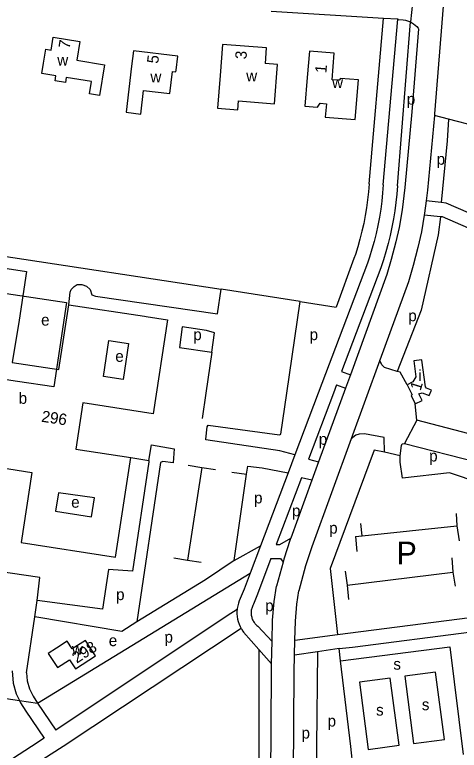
# Model space of a CAD drawing. Extents: x 161093 to 163177, y 379000 to 380904.
# Drawn here: x 162069 to 162225.3, y 380098.6 to 380357.5 of the extents above; entities that cross this region are included whole.
import ezdxf

# ---------------------------------------------------------------- set-up
doc = ezdxf.new("R2010")
doc.units = 0
for name, color, linetype in [('BLT_Basislijn', 7, 'Continuous'), ('BLT_Bebouwing', 7, 'Continuous'), ('BLT_Centroide', 7, 'Continuous'), ('BLT_Huisnummer', 7, 'Continuous'), ('BLT_Plantopo', 7, 'Continuous'), ('BLT_Tekst_parkeren', 7, 'Continuous'), ('BLT_Vlakafsluiter', 7, 'Continuous')]:
    doc.layers.add(name, color=color, linetype=linetype)

msp = doc.modelspace()

# ---------------------------------------------------------------- linework, layer by layer
at = {"layer": 'BLT_Basislijn'}
for p, q in [((162198.67, 380356.2), (162159.21, 380358.65)), ((162193.58, 380297.98), (162198.67, 380356.2)), ((162198.57, 380297.66), (162203.66, 380355.89)), ((162203.66, 380355.89), (162198.67, 380356.2)), ((162203.56, 380297.34), (162208.14, 380354.96)), ((162203.9, 380355.88), (162203.66, 380355.89)), ((162221.51, 380320.74), (162216.57, 380322.02)), ((162236.18, 380316.92), (162221.51, 380320.74)), ((162218.96, 380291.4), (162213.66, 380291.97)), ((162218.68, 380286.4), (162213, 380287.01)), ((162020.09, 380279.33), (162141.64, 380260.89)), ((162192.98, 380270.01), (162175.72, 380224.32)), ((162188.26, 380271.65), (162181.99, 380254.57)), ((162197.7, 380268.37), (162183.94, 380231.94)), ((162140.29, 380252.19), (162141.64, 380260.89)), ((162169.35, 380256.53), (162141.64, 380260.89)), ((162164.68, 380224.32), (162169.35, 380256.53)), ((162169.35, 380256.53), (162181.99, 380254.57)), ((162138.36, 380238.71), (162136.21, 380224.32)), ((162203.49, 380231.99), (162198.95, 380233.34)), ((162183.94, 380231.94), (162187, 380230.81)), ((162182.18, 380227.27), (162181.07, 380224.32)), ((162182.18, 380227.27), (162185.29, 380226.11)), ((162136.21, 380224.32), (162134.88, 380215.35)), ((162175.72, 380224.32), (162167.53, 380202.64)), ((162210.33, 380214.78), (162209.83, 380220.58)), ((162167.53, 380202.64), (162165.1, 380196.22)), ((162204.46, 380202.3), (162198.96, 380203.58)), ((162109.79, 380201.62), (162116.21, 380200.61)), ((162134.8, 380198.19), (162129.74, 380165.58)), ((162129.99, 380198.94), (162134.8, 380198.19)), ((162134.8, 380198.19), (162139.61, 380197.45)), ((162145.3, 380196.56), (162150.49, 380195.76)), ((162146.18, 380165.42), (162150.49, 380195.76)), ((162165.1, 380196.22), (162155.43, 380170.61)), ((162191.17, 380174.08), (162190.71, 380178.48)), ((162188.76, 380173.83), (162189.31, 380168.57)), ((162146.18, 380165.42), (162155.43, 380170.61)), ((162155.43, 380170.61), (162151.78, 380160.93)), ((162124.93, 380166.33), (162129.74, 380165.58)), ((162159.06, 380166.08), (162154.33, 380153.55)), ((162129.74, 380165.58), (162134.55, 380164.84)), ((162151.78, 380160.93), (162149.65, 380155.3)), ((162185.88, 380156.7), (162223.07, 380161.31)), ((162149.65, 380155.3), (162147.97, 380151.24)), ((162154.33, 380153.55), (162152.99, 380150.11)), ((162152.19, 380147.9), (162152.14, 380147.56)), ((162152.25, 380148.24), (162152.19, 380147.9)), ((162152.34, 380148.57), (162152.25, 380148.24)), ((162152.43, 380148.9), (162152.34, 380148.57)), ((162152.56, 380149.22), (162152.43, 380148.9)), ((162152.69, 380149.54), (162152.56, 380149.22)), ((162152.99, 380150.11), (162152.69, 380149.54)), ((162152.13, 380147.22), (162152.12, 380146.87)), ((162152.12, 380146.87), (162152.14, 380146.53)), ((162152.14, 380147.56), (162152.13, 380147.22)), ((162152.14, 380146.53), (162152.17, 380146.19)), ((162152.17, 380146.19), (162152.24, 380145.85)), ((162152.24, 380145.85), (162152.31, 380145.51)), ((162152.31, 380145.51), (162152.41, 380145.18)), ((162182.5, 380139.33), (162228.95, 380145.32)), ((162152.41, 380145.18), (162152.52, 380144.86)), ((162152.52, 380144.86), (162152.66, 380144.54)), ((162152.66, 380144.54), (162152.8, 380144.23)), ((162152.8, 380144.23), (162152.98, 380143.93)), ((162152.98, 380143.93), (162153.16, 380143.64)), ((162153.16, 380143.64), (162153.37, 380143.37)), ((162153.37, 380143.37), (162153.58, 380143.1)), ((162153.58, 380143.1), (162153.82, 380142.85)), ((162153.82, 380142.85), (162154.07, 380142.6)), ((162154.07, 380142.6), (162154.47, 380142.27)), ((162149.48, 380140.22), (162154.88, 380134.06)), ((162154.47, 380142.27), (162159.49, 380136.92)), ((162187.76, 380134.97), (162229.62, 380140.36)), ((162167.5, 380137.4), (162182.5, 380139.33)), ((162167.37, 380132.08), (162167.5, 380137.4)), ((162183.04, 380134.42), (162187.76, 380134.97)), ((162154.88, 380134.06), (162154.71, 380069.15)), ((162154.88, 380134.06), (162159.3, 380129.04)), ((162175.45, 380133.29), (162167.37, 380132.08)), ((162183.04, 380134.42), (162175.45, 380133.29)), ((162183.55, 380130.14), (162183.04, 380134.42))]:
    msp.add_line(p, q, dxfattribs=at)
for points in [[(162221.79, 380386.84), (162216.62, 380322.6), (162216.57, 380322.02)], [(162203.9, 380355.88), (162205.62, 380355.66), (162206.38, 380355.55), (162207.13, 380355.36), (162207.85, 380355.1), (162208.14, 380354.96)], [(162208.14, 380354.96), (162208.55, 380354.76), (162209.2, 380354.35), (162209.81, 380353.88), (162210.37, 380353.34), (162210.87, 380352.75), (162211, 380352.55)], [(162211, 380352.55), (162208.65, 380323.29), (162206.21, 380296.69), (162205.19, 380288.78), (162204.17, 380282.61), (162203, 380277.52), (162201.4, 380271.38), (162199.83, 380266.05), (162187, 380230.81)], [(162216.57, 380322.02), (162214.16, 380295.81), (162213.66, 380291.97)], [(162221.51, 380320.74), (162220.98, 380313.14), (162218.96, 380291.4)], [(162193.58, 380297.98), (162193.36, 380295.17), (162193.06, 380292.37), (162192.68, 380289.58), (162192.22, 380286.8), (162191.69, 380284.03), (162191.07, 380281.28), (162190.38, 380278.55), (162189.61, 380275.84), (162188.77, 380273.15), (162188.26, 380271.65)], [(162198.57, 380297.66), (162198.34, 380294.78), (162198.04, 380291.91), (162197.66, 380289.05), (162197.2, 380286.2), (162196.66, 380283.36), (162196.04, 380280.54), (162195.34, 380277.74), (162194.57, 380274.96), (162193.71, 380272.2), (162192.98, 380270.01)], [(162203.56, 380297.34), (162203.33, 380294.4), (162203.02, 380291.46), (162202.64, 380288.53), (162202.17, 380285.61), (162201.62, 380282.7), (162201, 380279.81), (162200.3, 380276.94), (162199.52, 380274.09), (162198.67, 380271.26), (162197.7, 380268.37)], [(162213.66, 380291.97), (162213.1, 380287.62), (162213, 380287.01)], [(162244.29, 380280.93), (162220.69, 380291.21), (162218.96, 380291.4)], [(162213, 380287.01), (162212.02, 380281.07), (162210.77, 380275.62), (162209.11, 380269.24), (162207.44, 380263.55), (162197.39, 380235.98)], [(162218.68, 380286.4), (162217.84, 380280), (162211.85, 380253.56), (162203.49, 380231.99)], [(162242.29, 380276.35), (162219.39, 380286.32), (162218.68, 380286.4)], [(162088.01, 380255.45), (162088.48, 380259.87), (162088.86, 380260.77), (162089.9, 380261.91), (162090.95, 380262.51), (162092.59, 380262.53), (162094.23, 380261.99), (162095.57, 380260.74), (162096.11, 380258.89), (162097.39, 380258.51), (162140.29, 380252.19)], [(162139.27, 380245.53), (162136.39, 380246.41), (162127.92, 380247.62), (162126.93, 380240.4), (162138.36, 380238.71)], [(162138.36, 380238.71), (162139.27, 380245.53)], [(162197.39, 380235.98), (162187.29, 380208.23)], [(162198.95, 380233.34), (162198.5, 380233.81), (162198.11, 380234.33), (162197.79, 380234.89), (162197.53, 380235.49), (162197.39, 380235.98)], [(162187, 380230.81), (162185.29, 380226.11)], [(162206.92, 380227.27), (162204.52, 380231.68), (162203.49, 380231.99)], [(162185.29, 380226.11), (162175.83, 380200.15)], [(162167.53, 380202.64), (162162.24, 380204.03), (162136.25, 380207.85), (162136.14, 380208.09), (162136.64, 380212.45), (162136.98, 380213.03), (162162.05, 380209.65), (162162.59, 380209.92), (162164.68, 380224.32)], [(162181.07, 380224.32), (162172.27, 380201.04), (162175.83, 380200.15)], [(162260.16, 380201.73), (162210.33, 380214.78)], [(162198.96, 380203.58), (162198.94, 380208.72), (162191.94, 380210.05), (162190.13, 380209.93), (162188.95, 380209.48), (162187.29, 380208.23)], [(162187.29, 380208.23), (162173.43, 380170.19), (162171.26, 380163.55), (162168.87, 380154.72)], [(162116.21, 380200.61), (162117.09, 380206.11), (162125.12, 380204.76), (162124.69, 380199.76)], [(162204.46, 380202.3), (162205.01, 380205.92), (162205.25, 380206.43), (162206.06, 380206.62)], [(162206.06, 380206.62), (162231.66, 380200.03)], [(162198.96, 380203.58), (162195.39, 380204.28), (162179.93, 380162.57), (162182.5, 380139.33)], [(162232.64, 380192.64), (162221.84, 380196.26), (162205.39, 380194.4), (162204.51, 380200.02), (162204.46, 380202.3)], [(162116.21, 380200.61), (162116.14, 380200.16), (162110.4, 380161.64), (162102.02, 380162.27), (162099.86, 380148.35), (162076.87, 380151.37)], [(162124.69, 380199.76), (162121.1, 380200.26), (162120.28, 380199.95), (162111.97, 380143.83)], [(162175.83, 380200.15), (162173.47, 380193.68)], [(162150.49, 380195.76), (162151.02, 380198.65), (162155.97, 380197.99), (162165.1, 380196.22)], [(162173.47, 380193.68), (162169.82, 380194.56), (162160.95, 380171.08)], [(162173.47, 380193.68), (162166.06, 380173.32)], [(162224.19, 380182), (162224.45, 380177.57), (162225.21, 380172.34)], [(162188.76, 380173.83), (162191.17, 380174.08), (162224.45, 380177.57)], [(162160.95, 380171.08), (162162.24, 380171.08), (162166.06, 380173.32)], [(162166.06, 380173.32), (162165.87, 380172.81), (162163.59, 380165.84), (162163.33, 380164.87)], [(162159.06, 380166.08), (162162.49, 380166.08), (162163.33, 380164.87)], [(162222.65, 380166.33), (162223.07, 380161.31), (162223.86, 380156.41)], [(162146.18, 380165.42), (162136.05, 380158.64), (162111.97, 380143.83)], [(162163.33, 380164.87), (162161.03, 380156.4)], [(162076.87, 380151.37), (162077.88, 380159.45), (162056.85, 380162.52)], [(162077.06, 380115.17), (162151.78, 380160.93)], [(162185.23, 380161.61), (162185.88, 380156.7), (162186.38, 380151.69)], [(162159.49, 380136.92), (162159.67, 380144.48), (162160.18, 380151.04), (162161.03, 380156.4)], [(162167.5, 380137.4), (162167.66, 380144.07), (162168.13, 380150.1), (162168.87, 380154.72)], [(162076.05, 380145.6), (162076.87, 380151.37)], [(162147.97, 380151.24), (162147.64, 380150.36), (162147.39, 380149.46), (162147.22, 380148.54), (162147.18, 380148.14)], [(162147.18, 380148.14), (162143.66, 380146), (162083.49, 380105.73)], [(162147.18, 380148.14), (162147.13, 380147.61), (162147.12, 380146.68), (162147.19, 380145.74), (162147.33, 380144.82), (162147.56, 380143.91), (162147.86, 380143.03), (162148.24, 380142.17), (162148.61, 380141.5)], [(162073.21, 380125.83), (162076.05, 380145.6)], [(162111.97, 380143.83), (162106.63, 380140.39), (162076.05, 380145.6)], [(162148.61, 380141.5), (162086.06, 380100), (162046.53, 380074.71)], [(162148.61, 380141.5), (162148.69, 380141.35), (162149.2, 380140.58), (162149.48, 380140.22)], [(162159.3, 380129.04), (162159.49, 380136.92)], [(162183.55, 380130.14), (162221.93, 380135.08), (162226.6, 380097.18)], [(162175.45, 380133.29), (162175.12, 380100), (162175.06, 380082.63)], [(162166.71, 380035.59), (162167.23, 380126.08), (162167.37, 380132.08)], [(162187.95, 380092.23), (162187.16, 380100), (162183.55, 380130.14)], [(162051.68, 380129.25), (162049.48, 380119.32), (162070.67, 380116.13)], [(162158.8, 380050.8), (162159.23, 380126.2), (162159.3, 380129.04)], [(162068.14, 380126.64), (162068.43, 380122.21), (162069.56, 380118.51), (162070.67, 380116.13)], [(162073.21, 380125.83), (162073.39, 380123.11), (162074.25, 380120.3), (162075.46, 380117.68), (162077.06, 380115.17)], [(162220.1, 380102.44), (162216.98, 380126.1), (162206.1, 380124.67), (162209.23, 380101.01), (162220.1, 380102.44)], [(162204.18, 380100.39), (162201.05, 380124.05), (162190.18, 380122.61), (162193.31, 380098.95), (162204.18, 380100.39)], [(162070.67, 380116.13), (162071.06, 380115.28), (162072.88, 380112.42), (162079.34, 380102.95)], [(162070.67, 380116.13), (162077.06, 380115.17)], [(162077.06, 380115.17), (162083.49, 380105.73)], [(162079.34, 380102.95), (162074.93, 380100), (161992.28, 380046.37), (161988.3, 380044.19), (161984.8, 380043.84), (161981.68, 380045.04), (161979.21, 380047.82), (161978.69, 380048.91)]]:
    msp.add_lwpolyline(points, dxfattribs=at)
at = {"layer": 'BLT_Bebouwing'}
for points in [[(162095.3, 380329.63), (162096.02, 380334.01), (162087.16, 380335.46), (162086.87, 380333.66), (162083.23, 380334.26), (162083.52, 380336.05), (162078.52, 380336.87), (162079.1, 380340.44), (162079.92, 380345.39), (162081.82, 380345.08), (162082.56, 380349.59), (162091.88, 380348.07), (162090.8, 380341.46), (162100.57, 380339.86), (162098.81, 380329.06), (162095.3, 380329.63)], [(162114.34, 380330.85), (162123.53, 380329.76), (162124.45, 380337.52), (162125.7, 380337.37), (162125.77, 380337.94), (162126.36, 380342.91), (162110.76, 380344.76), (162110.12, 380339.37), (162108.2, 380323.16), (162113.35, 380322.55), (162114.34, 380330.85)], [(162157.12, 380340.32), (162157.55, 380345.84), (162142.07, 380347.04), (162141.22, 380336.13), (162140.3, 380324.58), (162147.42, 380324.02), (162147.66, 380327.17), (162160.31, 380326.19), (162161.38, 380339.99), (162157.11, 380340.32)], [(162178.2, 380321.49), (162188.66, 380320.59), (162189.87, 380334.54), (162183.52, 380335.09), (162183.06, 380334.43), (162180.56, 380334.64), (162181.35, 380343.93), (162172.65, 380344.69), (162171.85, 380335.4), (162170.98, 380325.35), (162175.43, 380324.97), (162176.43, 380326.39), (162178.61, 380326.2), (162178.2, 380321.49)], [(162019.55, 380237.6), (162021.39, 380250.01), (162025.13, 380274.47), (162073.2, 380267.11), (162070.58, 380249.99), (162068.08, 380235.11), (162084.57, 380232.59), (162088.01, 380255.45)], [(162088.01, 380255.45), (162114.67, 380251.37), (162115.18, 380251.29), (162122.74, 380250.14), (162117.68, 380217.08), (162092.99, 380220.86), (162090.49, 380204.57), (162109.79, 380201.62)], [(162102.13, 380242.84), (162109.03, 380241.82), (162107.09, 380229.15), (162100.21, 380230.2), (162102.13, 380242.84)], [(162209.83, 380220.58), (162212.19, 380221.76), (162211.04, 380224.08), (162212.2, 380224.45), (162214.69, 380223.45), (162215.47, 380225.36), (162213.81, 380226.04), (162213.4, 380226.58), (162212.1, 380235.88), (162212.08, 380236.05), (162209.27, 380235.67), (162210.02, 380230.09), (162208.94, 380228.25), (162206.92, 380227.27)], [(162206.92, 380227.27), (162208.68, 380223.69), (162208.35, 380223.52), (162209.83, 380220.58)], [(162023.21, 380200.46), (162021.87, 380191.72), (162021.53, 380189.53), (162020.84, 380185.02), (162055.79, 380179.67), (162058.74, 380198.93), (162075.05, 380196.43), (162071.27, 380171.72), (162104.44, 380166.65), (162109.79, 380201.62)], [(162097.42, 380131.86), (162093.84, 380137.31), (162089.25, 380134.3), (162087.42, 380137.08), (162083.66, 380134.61)], [(162083.66, 380134.61), (162080.81, 380132.73), (162084.09, 380127.74), (162088.3, 380130.51), (162090.43, 380127.27), (162097.42, 380131.86)]]:
    msp.add_lwpolyline(points, dxfattribs=at)
msp.add_lwpolyline([(162084.4, 380189.29), (162083.4, 380182.74), (162095.99, 380180.81), (162097.01, 380187.52)], close=True, dxfattribs=at)
at = {"layer": 'BLT_Plantopo'}
msp.add_line((162082.8, 380226.57), (162069.94, 380228.4), dxfattribs=at)
msp.add_lwpolyline([(162069.94, 380228.4), (162025.54, 380235.2), (162030, 380264.81), (162087.26, 380256.18), (162082.8, 380226.57)], dxfattribs=at)
at = {"layer": 'BLT_Vlakafsluiter'}
for p, q in [((162208.84, 380361.58), (162208.14, 380354.96)), ((162210.33, 380214.78), (162206.06, 380206.62))]:
    msp.add_line(p, q, dxfattribs=at)

# ---------------------------------------------------------------- texts
at = {"layer": 'BLT_Centroide'}
for s, p in [('w', (162083.97, 380339.6)), ('w', (162150.39, 380334.03)), ('w', (162116.71, 380333.66)), ('w', (162180.58, 380331.69)), ('p', (162206.83, 380325.85)), ('p', (162217.34, 380304.71)), ('p', (162207.35, 380249.63)), ('e', (162078.29, 380248.11)), ('p', (162131.77, 380242.97)), ('p', (162172.67, 380242.97)), ('e', (162104.37, 380235.34)), ('i', (162210.94, 380228.54)), ('b', (162070.41, 380220.56)), ('p', (162175.91, 380206.16)), ('p', (162214.7, 380200.27)), ('e', (162088.86, 380184)), ('p', (162153.15, 380185.51)), ('p', (162166.49, 380180.98)), ('p', (162179.55, 380174.89)), ('p', (162104.65, 380151.48)), ('p', (162157.06, 380147.58)), ('e', (162102.08, 380135.28)), ('p', (162121.66, 380136.52)), ('w', (162089.12, 380132.28)), ('s', (162202.12, 380126.99)), ('s', (162212.12, 380112.74)), ('s', (162196.04, 380110.83)), ('p', (162178.99, 380106.98)), ('p', (162169.83, 380102.76))]:
    msp.add_text(s, height=4, dxfattribs=at).set_placement(p)
at = {"layer": 'BLT_Huisnummer'}
for s, rotation, p in [('7', 80.6967, (162088.3, 380345.34)), ('3', 85.5591, (162150.46, 380341.7)), ('5', 83.2346, (162119.44, 380340.14)), ('1', 85.0431, (162178.55, 380336.83)), ('1', 72.9284, (162211.68, 380224.95)), ('296', 351.2984, (162078.22, 380214.29)), ('298', 33.3329, (162090.85, 380129.08))]:
    msp.add_text(s, height=4, rotation=rotation, dxfattribs=at).set_placement(p)
at = {"layer": 'BLT_Tekst_parkeren'}
msp.add_text('P', height=8, dxfattribs=at).set_placement((162203.24, 380164.04))

doc.saveas('drawing.dxf')
